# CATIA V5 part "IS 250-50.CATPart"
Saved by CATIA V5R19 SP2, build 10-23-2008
Part number: IS 250-50
Bounding box of the stored display mesh (mm): x -18.951 to 18.951, y -18.952 to 18.952, z 0 to 150
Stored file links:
  C:\Users\Bora\Desktop\3D Katı model\IS serisi\IS 250\IS 250-50.CATPart
  C:\Program Files\Dassault Systemes\B19\intel_a\reffiles\standard\MetricThickPitch.txt
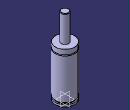
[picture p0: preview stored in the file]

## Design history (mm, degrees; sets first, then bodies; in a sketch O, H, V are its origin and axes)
Body1 (main body)
  Sketch1 on yz-plane, origin (0, 0, 0), H (0, 1, 0), V (0, 0, 1)
    point P3 (7.5, 149)
    point P5 (7.5, 149)
    point P7 (19, 88.5)
    point P8 (19, 86.5)
    point P12 (19, 86.5)
    point P13 (19, 88.5)
    line L1 (19, 0) -> (19, 4)
    line L2 (7.5, 149) -> (7.5, 98)
    arc A1 centre (6.5, 149) radius 1 from (7.5, 149) to (6.5, 150) ccw
    arc A2 centre (19, 87.5) radius 1 from (19, 88.5) to (19, 86.5) ccw
    line L3 (16.5, 7.5) -> (16.5, 4)
    line L4 (19, 7.5) -> (19, 86.5)
    line L5 (19, 88.5) -> (19, 98)
    line L6 (6.5, 150) -> (0, 150)
    point P15 (0, 150)
    line L7 (7.5, 98) -> (19, 98)
    line L8 (19, 0) -> (0, 0)
    line L9 (16.5, 4) -> (19, 4)
    line L10 (16.5, 7.5) -> (19, 7.5)
    tangency: L6 A1
    coincidence: P15 V, P3 P5, P7 P13, P8 P12
    horizontal: L7 H, L8 H, L9 H, L10 H
  Shaft1: profile Sketch1, axis Sketch1.V, angle 360
  Sketch2 on face of Shaft1 from Sketch1.L8, origin (0, 0, 0), H (1, 0, 0), V (0, -1, 0)
    point P1 (0, 0)
  Hole1: placed by Sketch2, at (0, 0, 0) direction (0, 0, 1), diameter 6.647, depth 7, threaded "M8", thread diameter 8, thread depth 7, pitch 1.25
